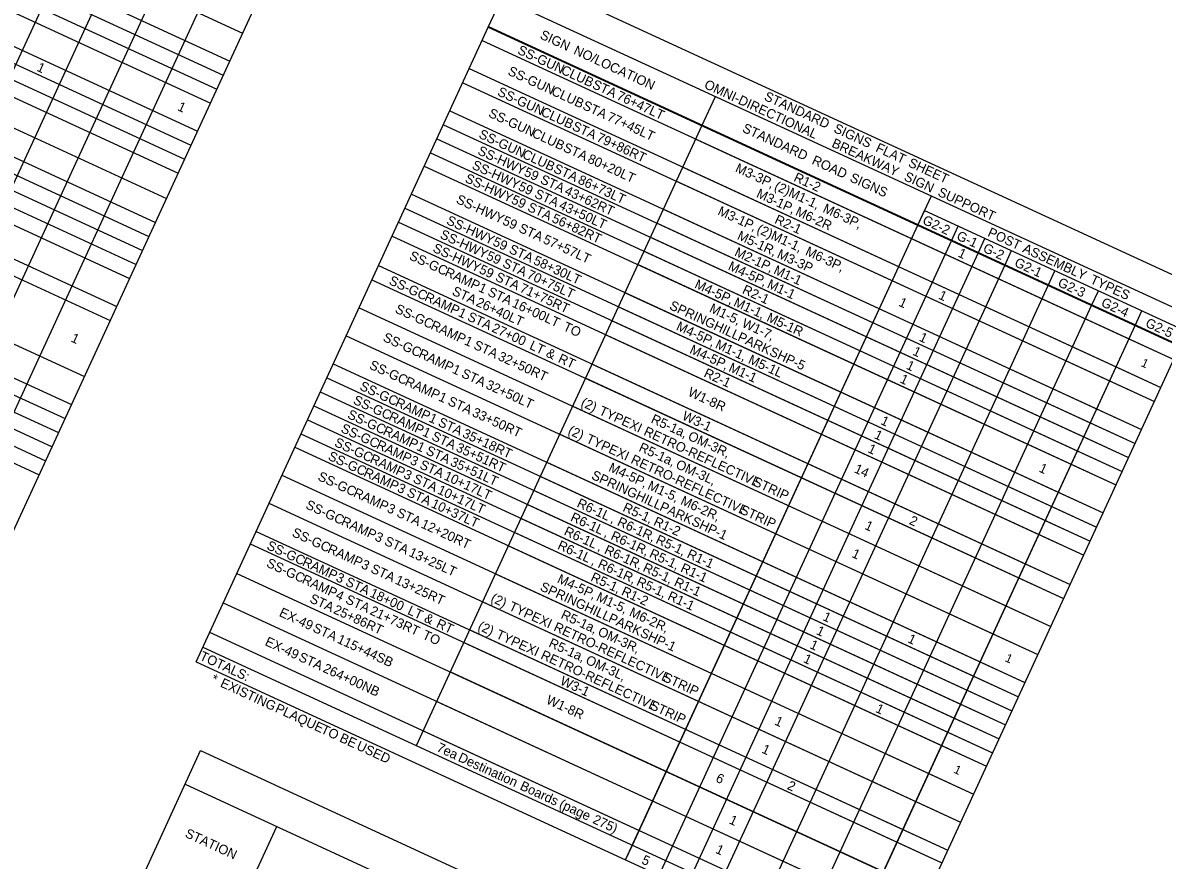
# Model space of a CAD drawing. Extents: x 627405 to 651306, y 367647 to 373471.
# Drawn here: x 650493 to 651034, y 372856 to 373252 of the extents above; entities that cross this region are included whole.
import ezdxf

# ---------------------------------------------------------------- set-up
doc = ezdxf.new("R2010")
doc.units = 0
doc.layers.add('Default', color=7, linetype='Continuous')

msp = doc.modelspace()

# ---------------------------------------------------------------- linework, layer by layer
at = {"layer": 'Default'}
for p, q in [((650269.84, 373398.35), (650597.59, 373247.32)), ((650263.72, 373385.06), (650591.46, 373234.03)), ((650260.66, 373378.42), (650588.4, 373227.39)), ((650257.6, 373371.78), (650585.34, 373220.75)), ((650254.54, 373365.14), (650582.28, 373214.11)), ((650248.42, 373351.86), (650576.16, 373200.83)), ((650245.35, 373345.22), (650573.1, 373194.19)), ((650300.65, 372821.34), (650539.21, 373339.03)), ((650242.29, 373338.57), (650570.04, 373187.54)), ((650239.23, 373331.93), (650566.98, 373180.9)), ((650321.24, 372811.86), (650559.79, 373329.55)), ((650233.73, 373319.98), (650561.47, 373168.95)), ((650341.83, 372802.37), (650580.38, 373320.06)), ((650383.67, 372783.09), (650631.25, 373320.37)), ((650228.52, 373308.69), (650556.27, 373157.66)), ((650225.46, 373302.05), (650553.21, 373151.02)), ((650362.41, 372792.88), (650597.76, 373303.6)), ((650362.41, 372792.88), (650597.76, 373303.6)), ((650222.4, 373295.41), (650550.15, 373144.38)), ((650219.34, 373288.76), (650547.09, 373137.74)), ((650216.28, 373282.12), (650544.03, 373131.09)), ((650713.97, 373250.05), (650726.21, 373276.61)), ((650726.21, 373276.61), (651053.96, 373125.58)), ((650210.16, 373268.84), (650537.91, 373117.81)), ((650720.39, 373263.99), (651048.14, 373112.97)), ((650207.1, 373262.2), (650534.85, 373111.17)), ((650575.49, 372949.53), (650714.12, 373250.38)), ((650713.97, 373250.05), (651041.72, 373099.02)), ((650714.12, 373250.38), (650714.12, 373250.38)), ((650714.12, 373250.38), (651041.87, 373099.35)), ((650711.06, 373243.74), (651038.81, 373092.71)), ((650194.86, 373235.63), (650522.61, 373084.6)), ((650704.94, 373230.46), (651032.69, 373079.43)), ((650188.74, 373222.35), (650516.49, 373071.32)), ((650701.88, 373223.81), (651029.63, 373072.79)), ((650185.68, 373215.71), (650513.43, 373064.68)), ((650815.25, 373203.38), (650821.67, 373217.32)), ((650695.76, 373210.53), (651023.51, 373059.5)), ((650182.62, 373209.07), (650510.37, 373058.04)), ((650692.7, 373203.89), (651020.45, 373052.86)), ((650179.56, 373202.43), (650507.3, 373051.4)), ((650679.98, 372909.83), (650815.4, 373203.71)), ((650176.5, 373195.79), (650504.24, 373044.76)), ((650689.64, 373197.25), (651017.39, 373046.22)), ((650812.34, 373197.07), (651017.56, 373102.5)), ((650173.44, 373189.14), (650501.18, 373038.12)), ((650686.58, 373190.61), (651014.33, 373039.58)), ((650683.67, 373184.3), (651011.42, 373033.27)), ((650806.22, 373183.79), (651011.44, 373089.22)), ((650803.16, 373177.14), (651008.37, 373082.58)), ((650677.55, 373171.02), (651005.3, 373019.99)), ((650917.52, 373156.25), (650923.95, 373170.19)), ((650674.49, 373164.37), (651002.24, 373013.35)), ((650797.04, 373163.86), (651002.25, 373069.3)), ((650917.52, 373156.25), (650920.74, 373163.22)), ((650920.74, 373163.22), (651044.93, 373105.99)), ((650671.43, 373157.73), (650999.18, 373006.7)), ((650779.04, 372855.73), (650917.68, 373156.58)), ((650782.25, 372862.7), (650917.68, 373156.58)), ((650793.98, 373157.22), (650999.19, 373062.65)), ((650933.46, 373148.9), (650936.68, 373155.88)), ((650668.37, 373151.09), (650996.12, 373000.06)), ((650790.92, 373150.58), (650996.13, 373056.01)), ((650946.08, 373143.09), (650949.29, 373150.06)), ((650794.98, 372848.38), (650933.62, 373149.23)), ((650787.86, 373143.94), (650993.07, 373049.37)), ((650807.6, 372842.57), (650946.23, 373143.42)), ((650958.7, 373137.27), (650961.91, 373144.25)), ((650661.94, 373137.15), (650989.69, 372986.12)), ((650784.95, 373137.63), (650990.17, 373043.06)), ((650820.22, 372836.75), (650958.85, 373137.61)), ((650979.29, 373127.79), (650982.5, 373134.76)), ((650658.88, 373130.5), (650986.63, 372979.48)), ((650778.83, 373124.35), (650984.04, 373029.78)), ((650840.81, 372827.27), (650979.44, 373128.12)), ((650999.88, 373118.3), (651003.09, 373125.27)), ((650775.77, 373117.7), (650980.98, 373023.14)), ((650861.39, 372817.78), (651000.03, 373118.63)), ((650652.76, 373117.22), (650980.51, 372966.19)), ((651020.46, 373108.81), (651023.68, 373115.79)), ((650772.71, 373111.06), (650977.92, 373016.5)), ((650881.98, 372808.29), (651020.62, 373109.14)), ((650901.26, 372850.13), (651020.62, 373109.14)), ((650646.64, 373103.94), (650974.39, 372952.91)), ((650769.65, 373104.42), (650974.86, 373009.86)), ((651017.56, 373102.5), (651038.81, 373092.71)), ((650906.45, 372805.47), (651041.87, 373099.35)), ((650640.52, 373090.66), (650968.27, 372939.63)), ((650763.22, 373090.47), (650968.44, 372995.91)), ((651011.44, 373089.22), (651032.69, 373079.43)), ((650637.46, 373084.02), (650965.21, 372932.99)), ((650760.16, 373083.83), (650965.38, 372989.27)), ((651008.37, 373082.58), (651029.63, 373072.79)), ((650634.4, 373077.37), (650962.15, 372926.34)), ((650631.34, 373070.73), (650959.09, 372919.7)), ((650754.04, 373070.55), (650959.26, 372975.99)), ((651002.25, 373069.3), (651023.51, 373059.5)), ((650628.28, 373064.09), (650956.03, 372913.06)), ((650999.19, 373062.65), (651020.45, 373052.86)), ((650625.22, 373057.45), (650952.96, 372906.42)), ((650747.92, 373057.27), (650953.14, 372962.7)), ((650996.13, 373056.01), (651017.39, 373046.22)), ((650622.31, 373051.14), (650950.06, 372900.11)), ((650993.07, 373049.37), (651014.33, 373039.58)), ((650741.8, 373043.99), (650947.01, 372949.42)), ((650990.17, 373043.06), (651011.42, 373033.27)), ((650616.19, 373037.86), (650943.94, 372886.83)), ((650738.74, 373037.34), (650943.95, 372942.78)), ((650735.68, 373030.7), (650940.89, 372936.14)), ((650984.04, 373029.78), (651005.3, 373019.99)), ((650610.07, 373024.58), (650937.82, 372873.55)), ((650732.62, 373024.06), (650937.83, 372929.5)), ((650980.98, 373023.14), (651002.24, 373013.35)), ((650729.56, 373017.42), (650934.77, 372922.86)), ((650977.92, 373016.5), (650999.18, 373006.7)), ((650603.95, 373011.29), (650931.7, 372860.26)), ((650726.5, 373010.78), (650931.71, 372916.21)), ((650974.86, 373009.86), (650996.12, 373000.06)), ((650601.19, 373005.32), (650928.94, 372854.29)), ((650723.59, 373004.47), (650928.81, 372909.9)), ((650968.44, 372995.91), (650989.69, 372986.12)), ((650594.77, 372991.37), (650922.51, 372840.34)), ((650717.47, 372991.19), (650922.68, 372896.62)), ((650965.38, 372989.27), (650986.63, 372979.48)), ((650588.34, 372977.42), (650916.09, 372826.39)), ((650711.35, 372977.91), (650916.56, 372883.34)), ((650959.26, 372975.99), (650980.51, 372966.19)), ((650581.91, 372963.48), (650909.66, 372812.45)), ((650705.23, 372964.62), (650910.44, 372870.06)), ((650953.14, 372962.7), (650974.39, 372952.91)), ((650578.7, 372956.5), (650906.45, 372805.47)), ((650702.47, 372958.65), (650907.69, 372864.08)), ((650575.49, 372949.53), (650903.23, 372798.5)), ((650696.05, 372944.7), (650901.26, 372850.13)), ((650947.01, 372949.42), (650968.27, 372939.63)), ((650943.95, 372942.78), (650965.21, 372932.99)), ((650940.89, 372936.14), (650962.15, 372926.34)), ((650689.62, 372930.75), (650874.25, 372845.67)), ((650937.83, 372929.5), (650959.09, 372919.7)), ((650934.77, 372922.86), (650956.03, 372913.06)), ((650683.19, 372916.81), (650867.82, 372831.73)), ((650931.71, 372916.21), (650952.96, 372906.42)), ((650497.93, 372734.46), (650577.65, 372907.47)), ((650577.65, 372907.47), (650577.65, 372907.47)), ((650577.65, 372907.47), (650888.79, 372764.09)), ((650928.81, 372909.9), (650950.06, 372900.11)), ((650922.68, 372896.62), (650943.94, 372886.83)), ((650570.3, 372891.53), (650881.45, 372748.15)), ((650916.56, 372883.34), (650937.82, 372873.55)), ((650596.67, 372834.29), (650613.8, 372871.48)), ((650910.44, 372870.06), (650931.7, 372860.26)), ((650907.69, 372864.08), (650928.94, 372854.29)), ((650779.04, 372855.73), (650782.25, 372862.7))]:
    msp.add_line(p, q, dxfattribs=at)

# ---------------------------------------------------------------- texts
for s, height, p in [('SIGN', 4.5, (650738.13, 373244.89)), ('SS-GUN', 4.5, (650727.47, 373237.72)), (' NO/LOCATION', 4.5, (650752.52, 373238.26)), ('1', 4.5, (650499.66, 373229.58)), ('SS-GUN', 4.5, (650722.88, 373227.76)), (' CLUB', 4.5, (650746.55, 373228.93)), ('SS-GUN', 4.5, (650717.95, 373217.96)), (' CLUB', 4.5, (650741.96, 373218.97)), (' STA', 4.5, (650761.35, 373222.11)), (' 76+47LT', 4.5, (650772.91, 373216.78)), ('OMNI-DIRECTIONAL', 4.5, (650815.93, 373221.43)), (' STA', 4.5, (650756.76, 373212.15)), ('STANDARD', 4.5, (650844.34, 373215.77)), ('1', 4.5, (650566.35, 373210.92)), ('SS-GUN', 4.5, (650713.7, 373207.84)), (' CLUB', 4.5, (650737.02, 373209.17)), (' 77+45LT', 4.5, (650768.32, 373206.82)), (' STA', 4.5, (650751.82, 373202.35)), ('STANDARD', 4.5, (650834, 373200.71)), (' SIGNS', 4.5, (650875.77, 373201.28)), ('SS-GUN', 4.5, (650709.11, 373197.88)), (' CLUB', 4.5, (650732.78, 373199.05)), (' 79+86RT', 4.5, (650763.39, 373197.02)), ('SS-HWY', 4.5, (650708.59, 373190.06)), (' STA', 4.5, (650747.58, 373192.23)), (' BREAKWAY', 4.5, (650874.83, 373194.28)), (' FLAT', 4.5, (650895.67, 373192.11)), (' CLUB', 4.5, (650728.19, 373189.08)), (' 80+20LT', 4.5, (650759.14, 373186.9)), (' ROAD', 4.5, (650865.44, 373186.22)), (' SHEET', 4.5, (650911.09, 373185.01)), ('SS-HWY', 4.5, (650705.88, 373183.26)), (' 59', 4.5, (650729.03, 373180.64)), (' STA', 4.5, (650742.99, 373182.27)), ('M3-3P,', 4.5, (650830.65, 373181.82)), ('SS-HWY', 4.5, (650702.55, 373176.95)), (' 59', 4.5, (650726.32, 373173.84)), (' STA', 4.5, (650736.69, 373177.12)), (' 86+73LT', 4.5, (650754.55, 373176.94)), (' (2)M1-1,', 4.5, (650847.63, 373173.99)), ('R1-2', 4.5, (650858.36, 373177.41)), (' SIGNS', 4.5, (650883.41, 373177.94)), (' SIGN', 4.5, (650909.08, 373178.5)), (' STA', 4.5, (650733.98, 373170.31)), (' 43+62RT', 4.5, (650748.25, 373171.79)), ('M3-1P,', 4.5, (650840.66, 373169.77)), (' SUPPORT', 4.5, (650925.11, 373171.11)), ('SS-HWY', 4.5, (650698.38, 373166.99)), (' 59', 4.5, (650722.99, 373167.53)), (' STA', 4.5, (650730.65, 373164)), (' 43+50LT', 4.5, (650745.54, 373164.99)), (' M6-3P,', 4.5, (650870.64, 373163.39)), ('SS-HWY', 4.5, (650693.79, 373157.03)), (' 59', 4.5, (650718.82, 373157.57)), (' 56+82RT', 4.5, (650742.21, 373158.67)), ('M3-1P,', 4.5, (650822.35, 373161.49)), ('R2-1', 4.5, (650849.28, 373157.44)), (' M6-2R', 4.5, (650857.63, 373161.95)), ('G2-2', 4.5, (650919.35, 373157.15)), (' STA', 4.5, (650726.48, 373154.04)), (' (2)M1-1,', 4.5, (650839.33, 373153.66)), ('POST', 4.5, (650950.26, 373151.37)), ('SS-HWY', 4.5, (650690.73, 373150.39)), (' 59', 4.5, (650714.23, 373147.61)), (' 57+57LT', 4.5, (650738.04, 373148.71)), ('M5-1R,', 4.5, (650831.57, 373149.81)), ('G-1', 4.5, (650935.51, 373149.71)), ('SS-HWY', 4.5, (650687.32, 373143.91)), (' STA', 4.5, (650721.89, 373144.08)), ('M2-1P,', 4.5, (650830.31, 373142.03)), (' M3-3P', 4.5, (650848.94, 373141.8)), (' M6-3P,', 4.5, (650862.33, 373143.06)), ('1', 4.5, (650936.15, 373141.57)), ('G-2', 4.5, (650948.04, 373143.93)), (' ASSEMBLY', 4.5, (650965.29, 373144.44)), ('SS-GC', 4.5, (650676.15, 373140.29)), (' 59', 4.5, (650711.17, 373140.97)), (' STA', 4.5, (650718.83, 373137.44)), (' 58+30LT', 4.5, (650733.45, 373138.75)), ('M4-5P,', 4.5, (650827.25, 373135.38)), ('G2-1', 4.5, (650962.94, 373137.07)), (' RAMP', 4.5, (650691.48, 373133.23)), (' 59', 4.5, (650707.76, 373134.49)), (' STA', 4.5, (650715.42, 373130.96)), (' 70+75LT', 4.5, (650730.39, 373132.11)), (' M1-1', 4.5, (650847.29, 373134.2)), ('SS-GC', 4.5, (650666.52, 373128.53)), (' 1', 4.5, (650707.43, 373125.88)), (' 71+75RT', 4.5, (650726.99, 373125.63)), ('M4-5P,', 4.5, (650811.38, 373126.8)), (' M1-1', 4.5, (650844.23, 373127.56)), ('G2-3', 4.5, (650983.49, 373127.6)), (' TYPES', 4.5, (650997.27, 373129.7)), (' RAMP', 4.5, (650681.85, 373121.47)), ('STA', 4.5, (650696.44, 373123.51)), (' STA', 4.5, (650711.79, 373123.87)), ('R2-1', 4.5, (650833.98, 373124.23)), ('1', 4.5, (650926.97, 373121.64)), ('SS-GC', 4.5, (650669.47, 373115.1)), (' 26+40LT', 4.5, (650706.25, 373118.99)), (' 16+00LT', 4.5, (650723.36, 373118.54)), ('SPRINGHILL', 4.5, (650799.43, 373116.71)), ('M1-5,', 4.5, (650818.38, 373115.41)), (' M1-1,', 4.5, (650828.35, 373118.97)), ('1', 4.5, (650908.1, 373118.26)), ('G2-4', 4.5, (651004.01, 373118.15)), (' 1', 4.5, (650697.8, 373114.12)), (' STA', 4.5, (650702.17, 373112.11)), (' W1-7,', 4.5, (650832.25, 373109.02)), (' M5-1R', 4.5, (650843.99, 373111.77)), ('G2-5', 4.5, (651025, 373108.47)), (' RAMP', 4.5, (650684.81, 373108.03)), (' 27+00', 4.5, (650713.73, 373106.78)), (' TO', 4.5, (650747.55, 373107.39)), ('M4-5P,', 4.5, (650802.67, 373106.86)), ('1', 4.5, (650515.85, 373101.34)), ('SS-GC', 4.5, (650663.7, 373101.65)), (' 1', 4.5, (650700.75, 373100.68)), (' STA', 4.5, (650705.12, 373098.67)), (' LT', 4.5, (650731.62, 373098.53)), (' M1-1,', 4.5, (650819.65, 373099.03)), (' PARK', 4.5, (650830.21, 373102.52)), ('1', 4.5, (650917.78, 373101.72)), (' RAMP', 4.5, (650679.03, 373094.59)), (' 32+50RT', 4.5, (650716.68, 373093.34)), (' &', 4.5, (650739.45, 373094.92)), ('M4-5P,', 4.5, (650809.04, 373095.87)), (' SHP-5', 4.5, (650845.32, 373095.56)), ('1', 4.5, (650914.72, 373095.08)), ('SS-GC', 4.5, (650657.23, 373088.53)), (' RT', 4.5, (650745.17, 373092.29)), (' M1-1', 4.5, (650826.02, 373088.05)), (' M5-1L', 4.5, (650835.28, 373091.83)), ('1', 4.5, (650911.66, 373088.43)), ('1', 4.12, (651022.92, 373089.71)), (' 1', 4.5, (650694.97, 373087.24)), (' STA', 4.5, (650699.34, 373085.23)), ('R2-1', 4.5, (650815.77, 373084.72)), ('1', 4.5, (650908.68, 373081.96)), ('SS-GC', 4.5, (650652.64, 373078.57)), (' RAMP', 4.5, (650672.56, 373081.46)), (' 32+50LT', 4.5, (650710.91, 373079.9)), ('W1-8R', 4.5, (650808.22, 373075.72)), ('SS-GC', 4.5, (650649.58, 373071.93)), (' RAMP', 4.5, (650667.97, 373071.5)), (' 1', 4.5, (650688.51, 373074.12)), (' STA', 4.5, (650692.88, 373072.1)), ('(2)', 4.5, (650757.48, 373070.82)), ('SS-GC', 4.5, (650646.86, 373065.13)), (' 33+50RT', 4.5, (650704.44, 373066.77)), (' TYPE', 4.5, (650764.56, 373067.56)), (' RAMP', 4.5, (650664.91, 373064.86)), (' 1', 4.5, (650683.92, 373064.15)), (' STA', 4.5, (650688.29, 373062.14)), (' XI', 4.5, (650778.9, 373060.95)), ('R5-1a,', 4.5, (650790.7, 373062.95)), ('W3-1', 4.5, (650805.49, 373064.49)), ('1', 4.5, (650899.57, 373062.2)), ('SS-GC', 4.5, (650643.74, 373058.52)), (' RAMP', 4.5, (650662.2, 373058.06)), (' 1', 4.5, (650680.86, 373057.51)), (' STA', 4.5, (650685.23, 373055.5)), (' 35+18RT', 4.5, (650699.85, 373056.81)), ('(2)', 4.5, (650751.36, 373057.54)), (' RETRO-REFLECTIVE', 4.5, (650785.76, 373057.79)), (' OM-3R,', 4.5, (650806.69, 373055.58)), ('1', 4.5, (650896.51, 373055.56)), ('SS-GC', 4.5, (650640.68, 373051.87)), (' RAMP', 4.5, (650659.07, 373051.45)), (' 1', 4.5, (650678.14, 373050.71)), (' 35+51RT', 4.5, (650696.79, 373050.17)), (' TYPE', 4.5, (650758.44, 373054.28)), ('R5-1a,', 4.5, (650784.93, 373049.51)), ('SS-GC', 4.5, (650637.69, 373045.4)), (' RAMP', 4.5, (650656.01, 373044.81)), (' STA', 4.5, (650682.51, 373048.7)), (' XI', 4.5, (650772.78, 373047.67)), (' RETRO-REFLECTIVE', 4.5, (650779.64, 373044.51)), ('1', 4.5, (650893.45, 373048.92)), (' 3', 4.5, (650675.01, 373044.1)), (' STA', 4.5, (650679.52, 373042.03)), (' 35+51LT', 4.5, (650694.08, 373043.37)), ('M4-5P,', 4.5, (650770.6, 373040)), (' OM-3L,', 4.5, (650800.91, 373042.14)), ('14', 4.5, (650887.02, 373039.4)), ('1', 4.5, (650974.56, 373039.72)), ('SS-GC', 4.5, (650632.83, 373035.76)), (' RAMP', 4.5, (650653.03, 373038.33)), (' 3', 4.5, (650671.95, 373037.46)), (' STA', 4.5, (650676.46, 373035.39)), (' 10+17LT', 4.5, (650691.08, 373036.7)), ('SPRINGHILL', 4.5, (650762.48, 373036.32)), (' STRIP', 4.5, (650837.54, 373033.93)), (' RAMP', 4.5, (650648.17, 373028.7)), (' 3', 4.5, (650668.97, 373030.99)), (' STA', 4.5, (650673.47, 373028.91)), (' 10+17LT', 4.5, (650688.02, 373030.06)), (' M1-5,', 4.5, (650787.58, 373032.18)), ('SS-GC', 4.5, (650627.06, 373022.32)), (' 10+37LT', 4.5, (650685.04, 373023.58)), ('R6-1L', 4.5, (650755.61, 373023.07)), (' M6-2R,', 4.5, (650803.21, 373024.98)), (' 3', 4.5, (650664.11, 373021.35)), (' STA', 4.5, (650668.61, 373019.27)), ('R6-1L', 4.5, (650752.55, 373016.43)), ('R5-1,', 4.5, (650777.36, 373021.09)), (' PARK', 4.5, (650793.27, 373022.13)), (' STRIP', 4.5, (650831.42, 373020.65)), (' RAMP', 4.5, (650642.39, 373015.25)), (' 12+20RT', 4.5, (650680.18, 373013.94)), (' ,', 4.5, (650770.05, 373016.41)), (' R6-1R,', 4.5, (650773.18, 373014.97)), (' R1-2', 4.5, (650790.4, 373015.09)), (' SHP-1', 4.5, (650808.37, 373015.17)), ('1', 4.5, (650891.99, 373012.55)), ('2', 4.5, (650913.09, 373014.91)), ('SS-GC', 4.5, (650620.59, 373009.2)), (' 3', 4.5, (650658.34, 373007.91)), ('R6-1L', 4.5, (650749.49, 373009.79)), (' ,', 4.5, (650766.99, 373009.77)), (' R6-1R,', 4.5, (650770.12, 373008.33)), (' R5-1,', 4.5, (650791.45, 373006.55)), ('SS-GC', 4.5, (650608.61, 373003.04)), (' RAMP', 4.5, (650635.92, 373002.13)), (' STA', 4.5, (650662.84, 373005.83)), ('R6-1L', 4.5, (650746.42, 373003.14)), (' R6-1R,', 4.5, (650767.06, 373001.69)), (' RAMP', 4.5, (650623.95, 372995.98)), (' 13+25LT', 4.5, (650674.41, 373000.5)), (' ,', 4.5, (650763.93, 373003.13)), (' R5-1,', 4.5, (650788.39, 372999.91)), (' R1-1', 4.5, (650806.24, 372999.74)), ('1', 4.5, (650885.87, 372999.27)), ('SS-GC', 4.5, (650608.47, 372994.75)), (' 3', 4.5, (650651.87, 372994.78)), (' STA', 4.5, (650656.37, 372992.71)), (' ,', 4.5, (650760.87, 372996.49)), (' R6-1R,', 4.5, (650763.99, 372995.05)), (' R5-1,', 4.5, (650785.33, 372993.27)), (' R1-1', 4.5, (650803.18, 372993.1)), (' RAMP', 4.5, (650623.8, 372987.68)), (' 3', 4.5, (650639.89, 372988.63)), (' STA', 4.5, (650644.39, 372986.55)), (' 13+25RT', 4.5, (650667.94, 372987.38)), ('M4-5P,', 4.5, (650746.27, 372987.2)), ('R5-1,', 4.5, (650762.14, 372988.05)), (' R5-1,', 4.5, (650782.27, 372986.63)), (' R1-1', 4.5, (650800.12, 372986.45)), (' 4', 4.5, (650639.75, 372980.33)), (' 18+00', 4.5, (650655.96, 372981.22)), ('SPRINGHILL', 4.5, (650738.15, 372983.52)), (' M1-5,', 4.5, (650763.25, 372979.38)), (' R1-2', 4.5, (650775.17, 372982.05)), (' R1-1', 4.5, (650797.06, 372979.81)), ('STA', 4.5, (650628.92, 372977.89)), (' STA', 4.5, (650644.43, 372978.18)), ('(2)', 4.5, (650714.79, 372978.18)), (' TYPE', 4.5, (650721.86, 372974.92)), ('EX-49', 4.5, (650614.54, 372971.32)), (' 25+86RT', 4.5, (650638.73, 372973.37)), (' 21+73RT', 4.5, (650656, 372972.85)), (' LT', 4.5, (650673.85, 372972.98)), (' &', 4.5, (650681.68, 372969.37)), (' XI', 4.5, (650736.21, 372968.31)), ('R5-1a,', 4.5, (650748.01, 372970.3)), (' PARK', 4.5, (650768.94, 372969.33)), (' M6-2R,', 4.5, (650778.88, 372972.18)), ('1', 4.5, (650872.1, 372969.39)), (' STA', 4.5, (650628.9, 372964.71)), (' RT', 4.5, (650687.4, 372966.74)), ('(2)', 4.5, (650708.67, 372964.9)), (' RETRO-REFLECTIVE', 4.5, (650743.07, 372965.15)), ('1', 4.5, (650869.04, 372962.74)), ('EX-49', 4.5, (650607.8, 372957.52)), (' 115+44SB', 4.5, (650640.46, 372959.38)), (' TO', 4.5, (650680.88, 372961.38)), (' TYPE', 4.5, (650715.74, 372961.63)), ('R5-1a,', 4.5, (650742.24, 372956.86)), (' OM-3R,', 4.5, (650763.99, 372962.94)), (' SHP-1', 4.5, (650784.04, 372962.37)), ('1', 4.5, (650912.35, 372958.89)), (' XI', 4.5, (650730.09, 372955.02)), ('1', 4.5, (650865.98, 372956.1)), ('TOTALS:', 4.5, (650576.82, 372950.67)), (' STA', 4.5, (650622.16, 372950.91)), (' RETRO-REFLECTIVE', 4.5, (650736.95, 372951.86)), (' OM-3L,', 4.5, (650758.22, 372949.49)), ('1', 4.5, (650862.92, 372949.46)), ('1', 4.12, (650958.5, 372949.91)), (' 264+00NB', 4.5, (650633.73, 372945.58)), ('*', 4.5, (650582.32, 372939.88)), (' EXISTING', 4.5, (650585.09, 372938.6)), ('W3-1', 4.5, (650747.65, 372938.97)), (' STRIP', 4.5, (650794.85, 372941.28)), ('W1-8R', 4.5, (650741.05, 372929.94)), (' PLAQUE', 4.5, (650611.1, 372926.62)), (' STRIP', 4.5, (650788.73, 372928)), ('1', 4.5, (650897.13, 372925.85)), ('1', 4.5, (650849.3, 372919.91)), (' TO', 4.5, (650632.76, 372916.64)), (' BE', 4.5, (650641.59, 372912.57)), (' USED', 4.5, (650649.63, 372908.86)), ('7ea', 4.5, (650689.18, 372907.34)), ('1', 4.5, (650843.18, 372906.63)), (' Destination', 4.5, (650697.8, 372903.37)), ('6', 4.5, (650821.4, 372892.91)), ('1', 4.12, (650934.17, 372897.11)), (' Boards', 4.5, (650727.09, 372889.87)), ('2', 4.5, (650855.24, 372889.39)), (' (page', 4.5, (650745.69, 372881.3)), (' 275)', 4.5, (650761.57, 372873.98)), ('1', 4.5, (650827.73, 372873.09)), ('STATION', 4.5, (650569.91, 372866.69)), ('5', 4.5, (650786.29, 372854.14)), ('1', 4.5, (650821.3, 372859.14))]:
    msp.add_text(s, height=height, rotation=335.2593, dxfattribs=at).set_placement(p)

doc.saveas('drawing.dxf')
